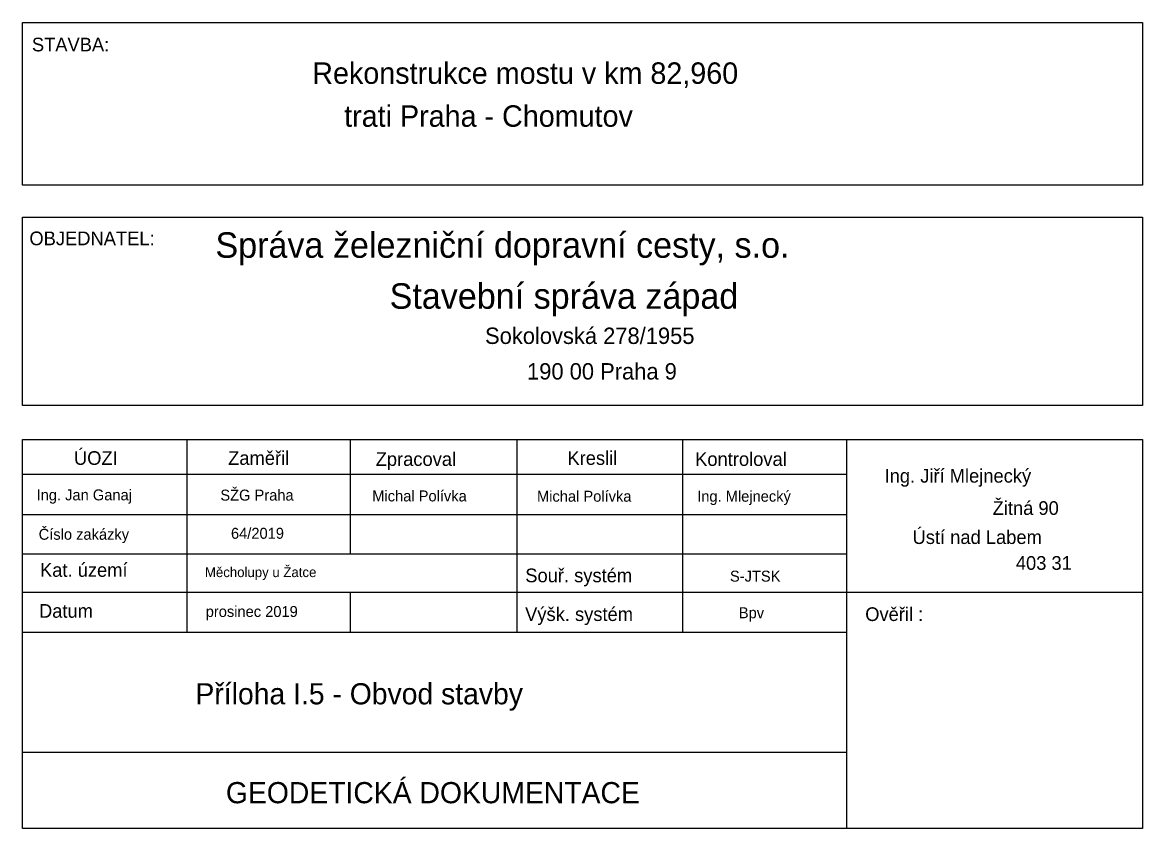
# Model space of a CAD drawing. Extents: x -879530 to -879371, y -1019242 to -1019127.
import ezdxf

# ---------------------------------------------------------------- set-up
doc = ezdxf.new("R2010")
doc.units = 0
doc.layers.add('LEGENDA', color=7, linetype='Continuous')
doc.layers.add('tabulka', color=7, linetype='Continuous')

msp = doc.modelspace()

# ---------------------------------------------------------------- linework, layer by layer
at = {"layer": 'tabulka'}
for p, q in [((-879530.09, -1019186.45), (-879371.44, -1019186.45)), ((-879506.8, -1019186.45), (-879506.8, -1019213.77)), ((-879483.66, -1019186.45), (-879483.66, -1019202.65)), ((-879460.06, -1019186.45), (-879460.06, -1019213.77)), ((-879436.61, -1019186.45), (-879436.61, -1019213.77)), ((-879413.31, -1019241.58), (-879413.31, -1019186.45)), ((-879530.09, -1019191.36), (-879413.31, -1019191.36)), ((-879530.09, -1019197.07), (-879413.31, -1019197.07)), ((-879530.09, -1019202.65), (-879413.31, -1019202.65)), ((-879530.09, -1019208.07), (-879371.44, -1019208.07)), ((-879483.66, -1019208.07), (-879483.66, -1019213.77)), ((-879530.09, -1019213.77), (-879413.31, -1019213.77)), ((-879530.09, -1019230.76), (-879413.31, -1019230.76))]:
    msp.add_line(p, q, dxfattribs=at)
for points in [[(-879530.09, -1019127.36), (-879371.44, -1019127.36), (-879371.44, -1019150.43), (-879530.09, -1019150.43)], [(-879530.09, -1019154.95), (-879371.44, -1019154.95), (-879371.44, -1019181.64), (-879530.09, -1019181.64)]]:
    msp.add_lwpolyline(points, close=True, dxfattribs=at)
msp.add_lwpolyline([(-879371.44, -1019186.45), (-879371.44, -1019241.58), (-879530.09, -1019241.58), (-879530.09, -1019186.45)], dxfattribs=at)

# ---------------------------------------------------------------- texts
at = {"layer": 'LEGENDA'}
for s, p in [('Rekonstrukce mostu v km 82,960 ', (-879489.04, -1019136.07)), ('    trati Praha - Chomutov', (-879489.04, -1019142.15))]:
    msp.add_text(s, height=3.04, dxfattribs=at).set_placement(p)
at = {"layer": 'tabulka'}
for s, height, p in [('STAVBA:', 1.94, (-879528.75, -1019131.47)), ('OBJEDNATEL:', 1.94, (-879529.1, -1019158.93)), ('Správa železniční dopravní cesty, s.o.', 3.61, (-879502.75, -1019160.71)), ('Stavební správa západ', 3.61, (-879478.08, -1019167.93)), ('Sokolovská 278/1955', 2.32, (-879464.57, -1019172.92)), ('190 00 Praha 9', 2.32, (-879458.62, -1019177.96)), ('ÚOZI', 1.94, (-879522.79, -1019190.05)), ('Zaměřil', 1.94, (-879500.95, -1019190.05)), ('Zpracoval', 1.94, (-879480.06, -1019190.2)), ('Kreslil', 1.94, (-879452.9, -1019190.05)), ('Kontroloval', 1.94, (-879434.81, -1019190.2)), ('Ing. Jiří Mlejnecký', 1.94, (-879407.98, -1019192.57)), ('Ing. Jan Ganaj', 1.552, (-879528.08, -1019195.08)), ('SŽG Praha', 1.552, (-879502.06, -1019195.11)), ('Michal Polívka', 1.552, (-879480.54, -1019195.23)), ('Michal Polívka', 1.552, (-879457.21, -1019195.27)), ('Ing. Mlejnecký', 1.552, (-879434.52, -1019195.27)), ('Žitná 90', 1.94, (-879392.68, -1019197.14)), ('Číslo zakázky', 1.552, (-879527.79, -1019200.66)), ('64/2019', 1.552, (-879500.55, -1019200.52)), ('Ústí nad Labem', 1.94, (-879404.02, -1019201.26)), ('403 31', 1.94, (-879389.39, -1019204.92)), ('Kat. území', 1.94, (-879527.6, -1019205.91)), ('Měcholupy u Žatce', 1.3968, (-879504.24, -1019205.95)), ('Souř. systém', 1.94, (-879458.87, -1019206.68)), ('S-JTSK', 1.552, (-879429.88, -1019206.59)), ('Datum', 1.94, (-879527.74, -1019211.71)), ('prosinec 2019', 1.552, (-879504.13, -1019211.6)), ('Výšk. systém', 1.94, (-879458.89, -1019212.17)), ('Bpv', 1.552, (-879428.62, -1019211.78)), ('Ověřil :', 1.94, (-879410.72, -1019212.17)), ('Příloha I.5 - Obvod stavby', 3, (-879505.58, -1019223.98)), ('GEODETICKÁ DOKUMENTACE ', 3, (-879501.27, -1019237.99))]:
    msp.add_text(s, height=height, dxfattribs=at).set_placement(p)

doc.saveas('drawing.dxf')
